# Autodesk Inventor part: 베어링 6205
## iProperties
Company: 한국ATC센터
IsCustomPart: 1
Created: 2009-02
Part Number: 베어링 6205
Material: 강, 연강
Description: 깊은 그루브 볼 베어링
Document SubType Name: Modeling
Standard: KS B 2023
Designer: KYOUNG IL JANG
Standards Organization: KS
Language: ko-KR
Size Designation: 6205 - 25 x 52 x 15
Categories: <MemberInstance><Categories><Category DisplayName="샤프트 부품" InternalName="7f7aeb1f-a693-4053-b835-cee3144e0d98" Mnemonic="SHFT"><Category DisplayName="베어링" Inter
Density: 1 g/cm^3
Author: KYOUNG IL JANG
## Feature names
1. IDS_ARRAYBALL[SIMPL:T] [Circular Pattern]
